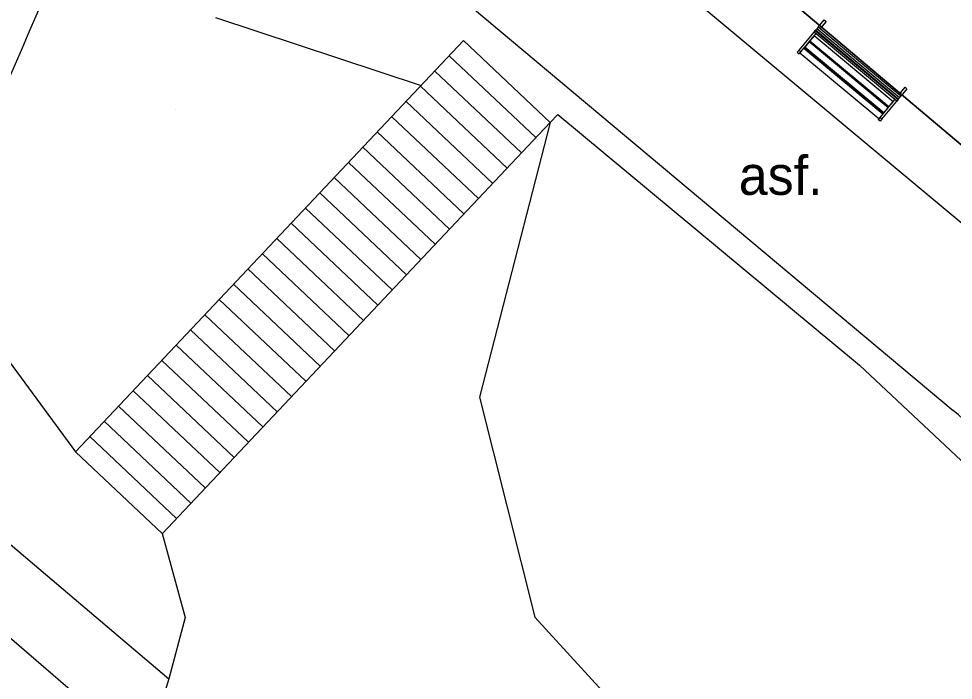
# Model space of a CAD drawing. Extents: x -438200 to -437954, y -1133133 to -1132850.
# Drawn here: x -438158.63 to -438143.01, y -1132970.08 to -1132959.02 of the extents above; entities that cross this region are included whole.
import ezdxf

# ---------------------------------------------------------------- set-up
doc = ezdxf.new("R2010")
doc.units = 0
for name, color, linetype in [('MOBILIÁŘ', 7, 'Continuous'), ('Vrstva 1', 7, 'Continuous'), ('Vrstva 10', 7, 'Continuous'), ('Vrstva 11', 7, 'Continuous'), ('Vrstva 14', 7, 'Continuous'), ('Vrstva 40', 7, 'Continuous')]:
    doc.layers.add(name, color=color, linetype=linetype)

# ---------------------------------------------------------------- blocks, each defined once
blk = doc.blocks.new('A$C6FF56919')
at = {"layer": 'Vrstva 1'}
for p, q in [((-17605, 5482), (-17605, 7031)), ((-401, 7031), (-401, 5482)), ((0, 7031), (-401, 7031)), ((0, 5482), (0, 7031)), ((-18000, 5423), (-18000, 5482)), ((-18000, 5482), (-17605, 5482)), ((-18000, 5423), (0, 5423)), ((-18000, 5108), (-18000, 5423)), ((-18000, 5108), (0, 5108)), ((-18000, 4771), (-18000, 5108)), ((-18000, 4771), (0, 4771)), ((-18000, 4707), (-18000, 4771)), ((0, 4707), (-18000, 4707)), ((-18000, 4707), (-18000, 4365)), ((-17605, 5423), (-17605, 5482)), ((-401, 5482), (0, 5482)), ((-401, 5423), (-401, 5482)), ((0, 5423), (0, 5482)), ((0, 5423), (0, 5108)), ((0, 5108), (0, 4771)), ((0, 4771), (0, 4707)), ((0, 4365), (0, 4707)), ((-18000, 459), (-18000, 4365)), ((-18000, 4365), (0, 4365)), ((-17605, 459), (-17605, 4365)), ((-17605, 3703), (-17594, 3703)), ((-17594, 2805), (-17594, 3895)), ((-401, 3703), (-411, 3703)), ((-401, 459), (-401, 4365)), ((0, 459), (0, 4365)), ((-17605, 2907), (-17594, 2907)), ((-17605, 2901), (-17594, 2901)), ((-17605, 2410), (-17594, 2410)), ((-17605, 1608), (-17594, 1608)), ((-17605, 1608), (-17594, 1608)), ((-411, 2805), (-17594, 2805)), ((-17594, 2805), (-17594, 2762)), ((-17594, 2762), (-411, 2762)), ((-17594, 2575), (-411, 2575)), ((-17594, 1475), (-17594, 2575)), ((-9200, 2575), (-9200, 2762)), ((-8799, 2575), (-8799, 2762)), ((-401, 2907), (-411, 2907)), ((-401, 2901), (-411, 2901)), ((-411, 2762), (-411, 2805)), ((-411, 2575), (-411, 1475)), ((-401, 2410), (-411, 2410)), ((-401, 1608), (-411, 1608)), ((-401, 1608), (-411, 1608)), ((-18000, 459), (-18000, 0)), ((-17605, 459), (-18000, 459)), ((-18000, 0), (-17605, 0)), ((-17605, 1106), (-17594, 1106)), ((-17605, 1106), (-17594, 1106)), ((-17605, 0), (-17605, 459)), ((-17605, 305), (-17594, 305)), ((-17594, 1459), (-17594, 1475)), ((-17594, 1475), (-411, 1475)), ((-411, 1459), (-17594, 1459)), ((-17594, 1245), (-17594, 1256)), ((-17594, 1256), (-411, 1256)), ((-17594, 1245), (-17594, 144)), ((-411, 1245), (-17594, 1245)), ((-17594, 144), (-411, 144)), ((-9200, 1256), (-9200, 1459)), ((-8800, 1256), (-8800, 1459)), ((-411, 1475), (-411, 1459)), ((-411, 1256), (-411, 1245)), ((-411, 144), (-411, 1245)), ((-401, 1106), (-411, 1106)), ((-401, 1106), (-411, 1106)), ((-401, 305), (-411, 305)), ((-401, 459), (0, 459)), ((-401, 0), (-401, 459)), ((0, 0), (-401, 0)), ((0, 459), (0, 0))]:
    blk.add_line(p, q, dxfattribs=at)
for points in [[(-17605, 7031), (-18000, 7031), (-18000, 5482)], [(-17594, 3895), (-411, 3895), (-411, 2805)]]:
    blk.add_lwpolyline(points, dxfattribs=at)

msp = doc.modelspace()

# ---------------------------------------------------------------- linework, layer by layer
at = {"layer": 'Vrstva 1'}
for p, q in [((-438152.337, -1132957.758), (-438143.007, -1132965.574)), ((-438152.337, -1132957.758), (-438143.007, -1132965.574)), ((-438151.196, -1132959.39), (-438151.196, -1132959.39)), ((-438151.914, -1132960.139), (-438151.914, -1132960.139)), ((-438156.01, -1132960.543), (-438156.01, -1132960.543)), ((-438149.622, -1132960.625), (-438149.622, -1132960.625)), ((-438154.531, -1132962.947), (-438154.531, -1132962.947)), ((-438144.574, -1132964.816), (-438144.574, -1132964.816)), ((-438150.927, -1132965.348), (-438150.927, -1132965.348)), ((-438157.683, -1132966.263), (-438157.683, -1132966.263)), ((-438155.851, -1132969.033), (-438155.851, -1132969.033)), ((-438150.005, -1132969.025), (-438150.005, -1132969.025)), ((-438156.123, -1132970.057), (-438156.123, -1132970.057))]:
    msp.add_line(p, q, dxfattribs=at)
msp.add_arc((-438146.86, -1132970.174), 6, 16.4456, 50.0448, dxfattribs=at)
msp.add_arc((-438146.86, -1132970.174), 6, 16.4456, 50.0448, dxfattribs=at)
at = {"layer": 'Vrstva 10'}
msp.add_arc((-438314.36, -1132892.214), 169.703, 333.204, 339.48146, dxfattribs=at)
at = {"layer": 'Vrstva 11'}
for points in [[(-438168.818, -1132951.108), (-438158.268, -1132965.467)], [(-438153.362, -1132953.683), (-438141.329, -1132963.718), (-438139.289, -1132965.196)], [(-438155.343, -1132959.004), (-438151.906, -1132960.142)], [(-438151.196, -1132959.39), (-438157.683, -1132966.263)], [(-438151.196, -1132959.39), (-438149.747, -1132960.758)], [(-438151.436, -1132959.644), (-438149.987, -1132961.012)], [(-438151.677, -1132959.899), (-438150.228, -1132961.267)], [(-438151.917, -1132960.153), (-438150.468, -1132961.521)], [(-438152.157, -1132960.408), (-438150.708, -1132961.776)], [(-438152.397, -1132960.662), (-438150.948, -1132962.03)], [(-438149.747, -1132960.758), (-438149.622, -1132960.625), (-438144.574, -1132964.816), (-438142.244, -1132966.996)], [(-438149.747, -1132960.758), (-438156.234, -1132967.631)], [(-438152.638, -1132960.917), (-438151.189, -1132962.285)], [(-438152.878, -1132961.171), (-438151.429, -1132962.539)], [(-438153.118, -1132961.426), (-438151.669, -1132962.794)], [(-438153.358, -1132961.68), (-438151.909, -1132963.048)], [(-438153.599, -1132961.935), (-438152.15, -1132963.303)], [(-438153.839, -1132962.189), (-438152.39, -1132963.557)], [(-438154.079, -1132962.444), (-438152.63, -1132963.812)], [(-438154.32, -1132962.698), (-438152.871, -1132964.066)], [(-438154.56, -1132962.953), (-438153.111, -1132964.321)], [(-438154.8, -1132963.207), (-438153.351, -1132964.575)], [(-438155.04, -1132963.462), (-438153.591, -1132964.83)], [(-438155.281, -1132963.716), (-438153.832, -1132965.084)], [(-438155.521, -1132963.971), (-438154.072, -1132965.339)], [(-438155.761, -1132964.225), (-438154.312, -1132965.593)], [(-438156.001, -1132964.48), (-438154.552, -1132965.848)], [(-438156.242, -1132964.734), (-438154.793, -1132966.102)], [(-438156.482, -1132964.989), (-438155.033, -1132966.357)], [(-438156.722, -1132965.243), (-438155.273, -1132966.611)], [(-438158.268, -1132965.467), (-438157.683, -1132966.261)], [(-438156.963, -1132965.498), (-438155.514, -1132966.866)], [(-438157.203, -1132965.752), (-438155.754, -1132967.12)], [(-438157.443, -1132966.007), (-438155.994, -1132967.375)], [(-438157.683, -1132966.261), (-438156.234, -1132967.629)], [(-438159.222, -1132967.431), (-438156.123, -1132970.057), (-438156.515, -1132971.329), (-438159.767, -1132968.525)], [(-438156.234, -1132967.629), (-438155.851, -1132969.033), (-438156.123, -1132970.057)]]:
    msp.add_lwpolyline(points, dxfattribs=at)
at = {"layer": 'Vrstva 14'}
msp.add_lwpolyline([(-438149.747, -1132960.758), (-438150.927, -1132965.348), (-438150.005, -1132969.025), (-438142.557, -1132977.168), (-438140.54, -1132981.557)], dxfattribs=at)
at = {"layer": 'Vrstva 40'}
for points in [[(-438149.086, -1132955.896), (-438140.718, -1132962.948), (-438137.827, -1132959.517), (-438146.195, -1132952.465)], [(-438146.195, -1132952.465), (-438137.827, -1132959.517), (-438140.718, -1132962.948), (-438149.086, -1132955.896)]]:
    msp.add_lwpolyline(points, close=True, dxfattribs=at)

# ---------------------------------------------------------------- block references
at = {"layer": 'MOBILIÁŘ', "xscale": 9.999999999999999e-05, "yscale": -9.999999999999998e-05, "rotation": 140.2266866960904}
msp.add_blockref('A$C6FF56919', (-438145.615, -1132959.585), dxfattribs=at)

# ---------------------------------------------------------------- texts
at = {"layer": 'Vrstva 40'}
msp.add_text('asf.', height=0.65, dxfattribs=at).set_placement((-438146.594, -1132961.968))

doc.saveas('drawing.dxf')
